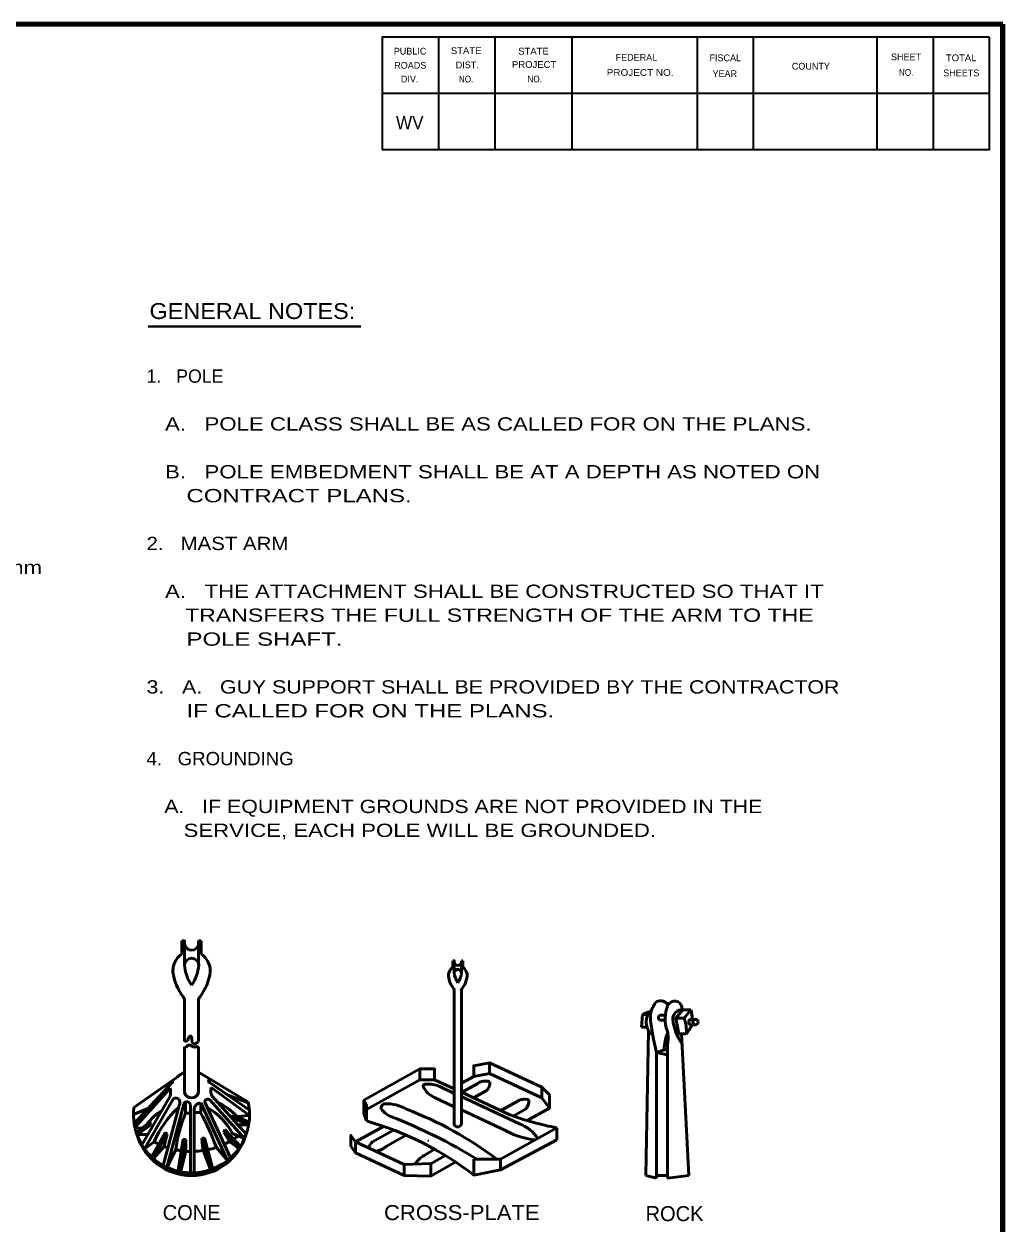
# Model space of a CAD drawing. Extents: x -34 to 821, y -14 to 530.
# Drawn here: x 593.8 to 814.9, y 252.8 to 523.9 of the extents above; entities that cross this region are included whole.
import ezdxf
from ezdxf.enums import TextEntityAlignment as Align

# ---------------------------------------------------------------- set-up
doc = ezdxf.new("R2010")
doc.units = 0
doc.header["$LTSCALE"] = 1.2
doc.layers.add('1', color=7, linetype='Continuous', lineweight=53)
doc.layers.add('61', color=7, linetype='Continuous', lineweight=35)

msp = doc.modelspace()

# ---------------------------------------------------------------- linework, layer by layer
at = {"layer": '1', "lineweight": 158}
msp.add_line((814.88, -2.224), (814.88, 523.876), dxfattribs=at)
at = {"layer": '1', "lineweight": 13}
for p, q in [((814.88, -2.224), (814.88, 523.876)), ((707.396, 276.19), (707.18, 276.07)), ((684.98, 271.462), (685.22, 271.87))]:
    msp.add_line(p, q, dxfattribs=at)
at = {"layer": '1', "lineweight": 40}
msp.add_line((621.793, 455.565), (669.856, 455.565), dxfattribs=at)
at = {"layer": '1'}
for p, q in [((629.42, 316.774), (629.42, 313.75)), ((630.019, 316.174), (630.019, 311.326)), ((633.212, 316.174), (633.212, 316.774)), ((633.212, 316.774), (633.812, 316.774)), ((633.212, 316.174), (633.212, 311.326)), ((633.812, 316.774), (633.812, 313.75)), ((690.644, 312.286), (690.644, 310.774)), ((690.956, 311.998), (690.956, 309.574)), ((692.54, 311.998), (692.54, 312.286)), ((692.54, 312.286), (692.851, 312.286)), ((692.54, 311.998), (692.54, 309.574)), ((692.851, 312.286), (692.851, 310.774)), ((690.956, 305.566), (690.956, 275.326)), ((692.54, 305.566), (692.54, 275.326)), ((630.019, 303.334), (630.019, 294.07)), ((633.188, 303.334), (633.188, 294.07)), ((733.484, 300.142), (733.196, 297.262)), ((734.707, 300.142), (733.484, 300.142)), ((738.62, 299.998), (737.3, 299.998)), ((738.524, 298.822), (737.3, 298.822)), ((745.46, 299.038), (744.236, 299.038)), ((734.396, 297.262), (733.196, 297.262)), ((734.228, 263.734), (734.803, 296.518)), ((742.268, 295.75), (741.668, 295.75)), ((743.947, 263.734), (742.268, 295.75)), ((742.268, 295.75), (743.348, 295.75)), ((745.46, 297.838), (744.236, 297.838)), ((630.019, 282.502), (630.019, 292.798)), ((633.188, 282.502), (633.188, 292.798)), ((739.076, 263.134), (739.076, 293.374)), ((736.652, 263.134), (736.652, 291.55)), ((736.652, 291.55), (739.076, 291.046)), ((683.18, 287.83), (670.484, 280.774)), ((698.923, 289.198), (710.707, 283.702)), ((628.052, 285.742), (618.596, 279.118)), ((627.188, 284.71), (618.644, 275.542)), ((633.163, 287.11), (644.348, 280.414)), ((635.803, 284.71), (644.659, 278.494)), ((683.18, 285.406), (671.084, 278.686)), ((686.492, 285.406), (690.932, 283.318)), ((695.348, 286.15), (692.54, 284.59)), ((695.348, 286.15), (698.923, 286.774)), ((698.923, 286.774), (710.707, 281.278)), ((626.755, 283.486), (618.812, 274.582)), ((636.019, 283.654), (644.707, 277.342)), ((644.348, 280.15), (639.572, 282.07)), ((687.668, 283.846), (690.956, 282.31)), ((692.54, 282.598), (703.484, 277.486)), ((696.236, 284.566), (692.611, 282.55)), ((698.156, 282.862), (695.324, 281.278)), ((710.707, 283.702), (710.707, 281.278)), ((626.755, 281.686), (620.396, 270.67)), ((627.524, 281.182), (620.971, 269.83)), ((628.82, 279.598), (625.196, 266.038)), ((629.851, 279.886), (626.012, 265.606)), ((630.236, 277.87), (630.236, 280.414)), ((631.34, 279.694), (631.34, 264.358)), ((633.668, 280.15), (639.692, 267.19)), ((634.58, 280.318), (640.436, 267.79)), ((635.755, 280.87), (643.58, 272.158)), ((636.236, 281.686), (643.94, 273.118)), ((686.516, 281.398), (690.956, 279.31)), ((692.516, 281.59), (705.692, 275.446)), ((705.163, 280.486), (701.444, 278.422)), ((618.476, 277.558), (621.74, 278.878)), ((630.236, 277.87), (631.34, 277.87)), ((632.204, 278.566), (632.204, 264.358)), ((640.988, 277.486), (644.42, 275.878)), ((640.988, 277.486), (641.012, 276.79)), ((641.012, 276.79), (644.396, 275.23)), ((644.707, 277.342), (641.827, 277.078)), ((692.54, 278.59), (702.788, 273.814)), ((707.036, 278.758), (704.228, 277.198)), ((618.812, 274.582), (620.3, 274.462)), ((619.004, 273.502), (622.196, 275.806)), ((619.364, 273.022), (622.388, 275.206)), ((622.196, 275.806), (622.388, 275.206)), ((639.139, 274.174), (638.923, 273.526)), ((639.139, 274.174), (642.572, 270.358)), ((644.396, 275.23), (642.043, 275.23)), ((677.252, 274.03), (672.476, 271.39)), ((714.115, 274.51), (714.115, 271.798)), ((619.364, 273.022), (621.812, 273.022)), ((620.971, 269.83), (623.156, 271.366)), ((622.532, 268.006), (625.676, 273.478)), ((622.988, 267.598), (626.132, 273.07)), ((626.132, 273.07), (625.436, 270.382)), ((625.676, 273.478), (626.132, 273.07)), ((629.731, 272.014), (628.604, 264.934)), ((630.308, 271.918), (629.204, 264.838)), ((629.731, 272.014), (630.308, 271.918)), ((630.308, 271.918), (630.308, 269.23)), ((634.556, 272.278), (633.956, 272.11)), ((633.956, 272.11), (635.803, 265.27)), ((633.956, 272.11), (634.172, 269.662)), ((634.556, 272.278), (636.356, 265.51)), ((638.923, 273.526), (642.115, 269.95)), ((640.148, 271.414), (638.923, 273.526)), ((642.115, 269.95), (640.148, 271.414)), ((643.58, 272.158), (640.868, 273.238)), ((668.635, 271.342), (679.604, 266.23)), ((668.635, 271.342), (668.635, 268.918)), ((680.108, 272.854), (675.668, 270.382)), ((622.988, 267.598), (625.46, 270.358)), ((626.012, 265.606), (628.028, 269.566)), ((629.204, 264.838), (630.308, 269.23)), ((635.803, 265.27), (634.172, 269.662)), ((639.692, 267.19), (637.22, 270.118)), ((686.516, 269.686), (684.139, 268.318)), ((679.604, 266.23), (685.652, 266.446)), ((679.604, 266.23), (679.604, 263.806)), ((691.268, 266.854), (685.652, 263.59)), ((685.652, 266.446), (685.652, 263.59)), ((688.916, 268.294), (685.676, 266.422)), ((701.42, 267.478), (701.42, 265.054)), ((679.604, 263.806), (685.652, 263.59)), ((734.228, 263.734), (736.652, 263.134)), ((736.652, 263.734), (739.076, 263.734)), ((739.076, 263.134), (743.947, 263.734))]:
    msp.add_line(p, q, dxfattribs=at)
at = {"layer": '1', "lineweight": 158}
msp.add_lwpolyline([(814.88, 523.876), (23.18, 523.776), (23.28, -2.224)], dxfattribs=at)
at = {"layer": '1'}
for points in [[(630.019, 316.174), (630.019, 316.774), (629.42, 316.774)], [(690.956, 311.998), (690.956, 312.286), (690.644, 312.286)], [(741.668, 295.75), (741.019, 299.326), (742.844, 299.326), (744.404, 301.174)], [(741.019, 299.326), (742.58, 301.174), (744.404, 301.174)], [(736.652, 291.55), (735.98, 294.574), (735.356, 298.15)], [(736.652, 291.55), (738.356, 292.174), (739.076, 292.174)], [(695.348, 286.15), (695.348, 288.55), (698.923, 289.198), (698.923, 286.774)], [(710.707, 283.198), (710.707, 283.702), (712.436, 282.022), (712.436, 278.998)], [(633.668, 280.15), (633.668, 277.966), (632.204, 277.966)], [(670.484, 280.774), (671.084, 279.742), (671.084, 276.094)], [(670.484, 280.774), (670.484, 277.75), (671.084, 276.094)], [(710.707, 281.278), (712.436, 278.998), (707.396, 276.19)], [(674.995, 274.87), (668.635, 271.342), (667.604, 272.83), (667.604, 270.406)], [(714.115, 274.51), (701.42, 267.478), (695.372, 267.478)], [(695.372, 267.478), (695.372, 263.854), (701.42, 265.054), (714.115, 271.798)], [(667.604, 270.406), (668.635, 268.918), (679.604, 263.806)]]:
    msp.add_lwpolyline(points, dxfattribs=at)
msp.add_lwpolyline([(686.492, 285.406), (686.492, 287.83), (683.18, 287.83), (683.18, 285.406)], close=True, dxfattribs=at)
msp.add_circle((745.429, 298.444), 0.605, dxfattribs=at)
for centre, radius, start, end in [((631.622, 316.258), 1.598, 183.14868, 356.60343), ((631.811, 309.968), 4.425, 144.42176, 182.06662), ((630.952, 311.011), 3.139, 119.19068, 150.80932), ((631.621, 311.237), 1.598, 3.15687, 176.59703), ((632.264, 311.011), 3.139, 29.19068, 60.80932), ((631.405, 309.968), 4.425, 357.93338, 35.57824), ((691.746, 312.037), 0.799, 183.14868, 356.60343), ((638.61, 311.1), 11.296, 186.56595, 218.44896), ((638.749, 311.843), 8.738, 183.35766, 215.34932), ((624.494, 311.836), 8.738, 324.65068, 356.64234), ((624.605, 311.1), 11.296, 321.55104, 353.43405), ((691.84, 308.892), 2.213, 144.42176, 182.06662), ((691.411, 309.414), 1.57, 119.19068, 150.80932), ((691.746, 309.527), 0.799, 3.15687, 176.59703), ((695.31, 309.83), 4.369, 183.35766, 215.34932), ((688.182, 309.827), 4.369, 324.65068, 356.64234), ((692.067, 309.414), 1.57, 29.19068, 60.80932), ((691.638, 308.892), 2.213, 357.93338, 35.57824), ((695.24, 309.458), 5.648, 186.56595, 218.44896), ((688.238, 309.458), 5.648, 321.55104, 353.43405), ((628.816, 303.324), 1.21, 0, 38.44896), ((634.4, 303.324), 1.21, 141.55104, 180), ((690.343, 305.57), 0.605, 0, 38.44896), ((693.135, 305.57), 0.605, 141.55104, 180), ((737.918, 298.387), 3.639, 130.0252, 235.18403), ((740.424, 299.482), 5.189, 136.6517, 167.95246), ((737.521, 301.349), 1.906, 27.27122, 117.20122), ((746.473, 299.167), 7.907, 156.78247, 200.56684), ((743.418, 299.238), 5.198, 137.75004, 144.12043), ((740.702, 301.455), 1.707, 354.19595, 131.52888), ((742.365, 299.089), 2.092, 84.04734, 179.89391), ((737.974, 299.233), 6.708, 358.55245, 16.7912), ((735.76, 296.681), 4.135, 98.89517, 123.27294), ((746.881, 299.356), 11.596, 174.01262, 185.98737), ((737.868, 299.413), 0.805, 133.97941, 226.02058), ((754.566, 301.117), 14.436, 188.05699, 211.90806), ((735.173, 296.395), 8.206, 355.44941, 20.86555), ((744.671, 298.439), 0.741, 125.33791, 234.66209), ((748.46, 292.069), 10.106, 157.16459, 179.40955), ((732.325, 294.879), 6.912, 347.36391, 12.63609), ((734.701, 302.701), 11.102, 321.19678, 333.99968), ((627.131, 284.893), 0.201, 285.47106, 119.84894), ((633.727, 279.723), 8.27, 116.58954, 133.41014), ((635.801, 285.057), 0.358, 72.34222, 272.05741), ((697.965, 282.11), 3.002, 70.73362, 125.44724), ((696.475, 284.708), 2.492, 312.2199, 5.43688), ((623.242, 282.583), 3.634, 345.54353, 14.45647), ((631.609, 282.941), 1.641, 195.24731, 344.75269), ((638.767, 282.955), 2.834, 165.83192, 206.84011), ((684.41, 283.949), 0.463, 85.12517, 207.35251), ((688.253, 285.772), 4.714, 204.55458, 248.28903), ((684.847, 277.138), 7.285, 67.29002, 93.88305), ((631.601, 277.47), 13.104, 172.76636, 12.86069), ((627.949, 279.545), 1.7, 63.18198, 104.27978), ((627.355, 280.22), 1.6, 336.72582, 31.75765), ((630.58, 279.661), 0.768, 2.53809, 163.55027), ((633.633, 278.712), 1.436, 89.05434, 186.28866), ((635.319, 280.253), 0.745, 54.79805, 174.78973), ((631.44, 267.735), 13.982, 41.97741, 64.76098), ((675.386, 279.008), 0.965, 94.88611, 188.90189), ((675.641, 271.162), 8.814, 59.08543, 92.19679), ((706.821, 277.998), 3.002, 70.73362, 125.44724), ((705.33, 280.596), 2.492, 312.2199, 5.43688), ((632.187, 267.254), 13.384, 122.96526, 142.37873), ((642.685, 263.34), 21.105, 131.72438, 157.64771), ((661.24, 265.155), 33.504, 157.68458, 172.42454), ((579.202, 248.538), 61.896, 20.41201, 28.38414), ((628.406, 266.852), 13.991, 27.13242, 61.23505), ((678.245, 281.338), 4.548, 213.03543, 254.05828), ((630.202, 158.95), 126.953, 58.74865, 68.37109), ((650.699, 201.241), 82.898, 53.04115, 69.17556), ((728.181, 345.673), 72.528, 250.09888, 258.8259), ((650.925, 205.902), 73.04, 52.50633, 73.9788), ((691.739, 275.545), 0.82, 195.19877, 344.80123), ((710.583, 287.969), 16.172, 241.1379, 265.46719), ((702.498, 267.205), 8.843, 33.93256, 68.86981), ((631.601, 276.576), 12.815, 196.98242, 343.01758), ((631.601, 286.743), 17.539, 241.25089, 244.7288), ((631.601, 286.743), 17.539, 294.68825, 298.86032), ((631.601, 286.743), 17.539, 302.79246, 306.95206), ((674.178, 269.41), 2.611, 130.48502, 167.67788), ((631.601, 286.743), 17.539, 249.43644, 252.21677), ((631.601, 286.743), 17.539, 258.07352, 262.19692), ((631.601, 286.743), 17.539, 265.78587, 269.16942), ((631.601, 286.743), 17.539, 271.8867, 278.3643), ((631.601, 286.743), 17.539, 282.12514, 288.50814), ((671.834, 275.212), 6.156, 282.65039, 308.50672), ((687.562, 262.688), 6.586, 121.25992, 146.56057)]:
    msp.add_arc(centre, radius, start, end, dxfattribs=at)
for points in [[(630.019, 294.07), (630.548, 294.166), (630.86, 294.622), (631.172, 295.15), (631.484, 295.246), (631.652, 294.742), (631.652, 294.31), (631.796, 293.902), (632.108, 293.542), (632.587, 293.59), (633.043, 293.998), (633.188, 294.07)], [(630.019, 292.798), (630.356, 292.798), (630.596, 292.918), (630.812, 293.206), (631.052, 293.254), (631.436, 293.158), (631.652, 292.966), (632.156, 292.798), (632.539, 292.798), (633.188, 292.798)]]:
    msp.add_spline(points, degree=3, dxfattribs=at)
at = {"layer": '61'}
for p, q in [((687.38, 520.876), (687.38, 495.476)), ((700.08, 520.876), (700.08, 495.476)), ((717.48, 520.876), (717.48, 495.476)), ((745.779, 520.876), (745.779, 495.476)), ((758.48, 520.876), (758.48, 495.476)), ((786.38, 520.876), (786.38, 495.476)), ((799.08, 520.876), (799.08, 495.476)), ((811.779, 508.176), (674.68, 508.176))]:
    msp.add_line(p, q, dxfattribs=at)
for points in [[(811.779, 520.876), (674.68, 520.876), (674.68, 495.476)], [(811.779, 520.876), (811.779, 495.476), (674.68, 495.476)]]:
    msp.add_lwpolyline(points, dxfattribs=at)

# ---------------------------------------------------------------- texts
at = {"layer": '1'}
for s, height, width, p in [('WV', 3.048, 0.95, (677.779, 500.076)), ('GENERAL NOTES:', 3.6, 1.1, (622.097, 457.233)), ('   A.   POLE CLASS SHALL BE AS CALLED FOR ON THE PLANS.', 3, 1.25, (621.438, 432.039)), ('   B.   POLE EMBEDMENT SHALL BE AT A DEPTH AS NOTED ON', 3, 1.25, (621.438, 421.239)), ('      CONTRACT PLANS.', 3, 1.35, (621.438, 415.839)), ('2.   MAST ARM', 3, 1.15, (621.438, 405.039)), ('9.525mmx63.5mm', 3, 1.25, (556.323, 399.627)), ('   A.   THE ATTACHMENT SHALL BE CONSTRUCTED SO THAT IT', 3, 1.25, (621.438, 394.239)), ('      TRANSFERS THE FULL STRENGTH OF THE ARM TO THE', 3, 1.3, (621.438, 388.839)), ('      POLE SHAFT.', 3, 1.35, (621.438, 383.439)), ('3.   A.   GUY SUPPORT SHALL BE PROVIDED BY THE CONTRACTOR', 3, 1.2, (621.438, 372.639)), ('      IF CALLED FOR ON THE PLANS.', 3, 1.35, (621.438, 367.239)), ('4.   GROUNDING', 3, 1.05, (621.438, 356.439)), ('   A.   IF EQUIPMENT GROUNDS ARE NOT PROVIDED IN THE', 3, 1.2, (621.438, 345.639)), ('      SERVICE, EACH POLE WILL BE GROUNDED.', 3, 1.25, (621.438, 340.239))]:
    msp.add_text(s, height=height, dxfattribs=dict(at, width=width)).set_placement(p)
msp.add_text('1.   POLE', height=3, dxfattribs=at).set_placement((621.438, 442.839))
for s, p in [('CONE', (631.63, 253.702)), ('ROCK', (740.694, 253.462))]:
    msp.add_text(s, height=3.387, dxfattribs=at).set_placement(p, align=Align.CENTER)
at = {"layer": '1', "width": 1.1}
msp.add_text('CROSS-PLATE', height=3.387, dxfattribs=at).set_placement((692.648, 253.702), align=Align.CENTER)
at = {"layer": '61'}
for s, height, rotation, p in [('PUBLIC', 1.525, 0.033, (677.279, 516.976)), ('ROADS', 1.525, 0.124, (677.38, 513.776)), ('DIST.', 1.525, 0.056, (691.279, 513.876)), ('FEDERAL', 1.523, 0.007, (727.38, 515.576)), ('FISCAL', 1.525, 359.942, (748.58, 515.476)), ('COUNTY', 1.523, 0.069, (767.18, 513.576)), ('SHEET', 1.525, 0.059, (789.58, 515.676)), ('YEAR', 1.523, 0.105, (749.279, 511.876)), ('SHEETS', 1.523, 359.959, (801.38, 512.076)), ('DIV.', 1.525, 359.932, (678.88, 510.676))]:
    msp.add_text(s, height=height, rotation=rotation, dxfattribs=at).set_placement(p)
for s, rotation, width, p in [('STATE', 0.059, 1.05, (690.18, 517.076)), ('STATE', 0.059, 1.05, (705.38, 516.976)), ('PROJECT', 359.908, 1.05, (703.98, 513.976)), ('TOTAL', 359.926, 1.05, (801.98, 515.476)), ('PROJECT NO.', 359.922, 1.1, (725.38, 512.176)), ('NO.', 359.852, 0.9, (791.38, 512.176)), ('NO.', 359.852, 0.9, (691.98, 510.676)), ('NO.', 0.225, 0.9, (707.48, 510.676))]:
    msp.add_text(s, height=1.525, rotation=rotation, dxfattribs=dict(at, width=width)).set_placement(p)

doc.saveas('drawing.dxf')
